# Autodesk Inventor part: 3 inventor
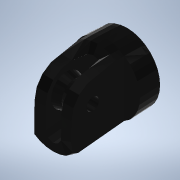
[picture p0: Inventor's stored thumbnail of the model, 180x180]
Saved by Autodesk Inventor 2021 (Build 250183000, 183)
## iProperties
Created: 2022-10
Part Number: 3 inventor
Material: Hierro, maleable
Document SubType Name: Modeling
Designer: Yair Obed
Density: 7.15 g/cm^3
Appearance: Semipulido
Author: Yair Obed
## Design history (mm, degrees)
node "3"
  node "MeshFeature1"
